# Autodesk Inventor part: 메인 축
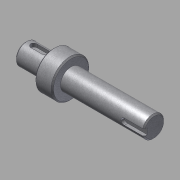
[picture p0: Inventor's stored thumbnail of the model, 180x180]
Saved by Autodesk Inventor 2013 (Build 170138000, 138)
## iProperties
Created: 2014-10
Part Number: 메인 축
Document SubType Name: Modeling
Designer: KYOUNG IL JANG
Density: 7.86 g/cm^3
Mass: 230.24 g
Surface Area: 74.3518 cm^2
Volume: 29.2926 cm^3
Material: 강철, 연강
Author: SeoGD™ [www.esajin.kr]
Revision Number: 1
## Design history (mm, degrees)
sketch "스케치1"
  geometry: L1 (10.497, -57.5)-(112.497, -57.5); L2 (10.497, -66)-(32.497, -66); L3 (32.497, -72.5)-(46.5, -72.5); L4 (46.5, -66)-(112.497, -66); L5 (112.497, -66)-(112.497, -57.5); L6 (10.497, -66)-(10.497, -57.5); L7 (46.5, -69.749)-(46.5, -45.251) reference; L8 (46.5, -72.5)-(46.5, -66); L9 (32.497, -72.5)-(32.497, -66); L10 (32.497, -35)-(32.497, -80) reference; 3 further points
  constraints: 16 end point, 3 point on line, 2 parallel, 2 perpendicular, 1 collinear, 1 horizontal, 1 midpoint
  dimensions: "d0" = 17 diameter of L4 L1; "d1" = 30 diameter of L3 L1; "d2" = 22 distance of L2.start L2.end; "d3" = 65.99692 distance of L4.start L4.end (derived); "d5" = 17 diameter of L2 L1; "d19" = 80 distance between parallel lines of L5 L9
revolve "회전1" sketch "스케치1" stored, may be unused: angle "d4" = 90 deg
chamfer "모따기1" distance "d6" = 1; stored, may be unused: second distance "d7" = 2, angle "d8" = 45 deg
node "작업 평면1"
sketch "스케치2"
  geometry: L1 (-11, -7.5)-(-11, 7.5) reference; L2 (-4.5, 2.5)-(4.5, 2.5); L3 (4.5, -2.5)-(-4.5, -2.5); A1 r 2.5 centre (4.5, 0) between (4.5, -2.5) and (4.5, 2.5); A2 r 2.5 centre (-4.5, 0) between (-4.5, 2.5) and (-4.5, -2.5); 2 further points
  constraints: 4 end point, 4 point on circle, 4 tangent, 2 centre point, 1 horizontal alignment, 1 midpoint, 1 parallel, 1 perpendicular
  dimensions: "d9" = 5 distance between parallel lines of L3 L2; "d10" = 14 dimension on A1 A2; "d11" = 4 distance edge to line of A2 L1
extrude "돌출1" cut sketch "스케치2" distance "d12" = 3; taper "d13" = 0 deg
node "작업 평면2"
sketch "스케치3"
  geometry: L1 (32.998, 7.5)-(32.998, -7.5) reference; L2 (32.998, 2.5)-(17.498, 2.5); L3 (17.498, -2.5)-(32.998, -2.5); A1 r 2.5 centre (17.498, 0) between (17.498, 2.5) and (17.498, -2.5); 2 further points
  constraints: 4 end point, 2 perpendicular, 2 point on circle, 2 point on line, 2 tangent, 1 centre point, 1 horizontal alignment, 1 midpoint
  dimensions: "d14" = 5 distance between parallel lines of L3 L2; "d15" = 18 dimension on A1 L1
extrude "돌출2" cut sketch "스케치3" distance "d16" = 3; taper "d17" = 0 deg
node "솔리드1"
node "참조4"
node "참조5"
